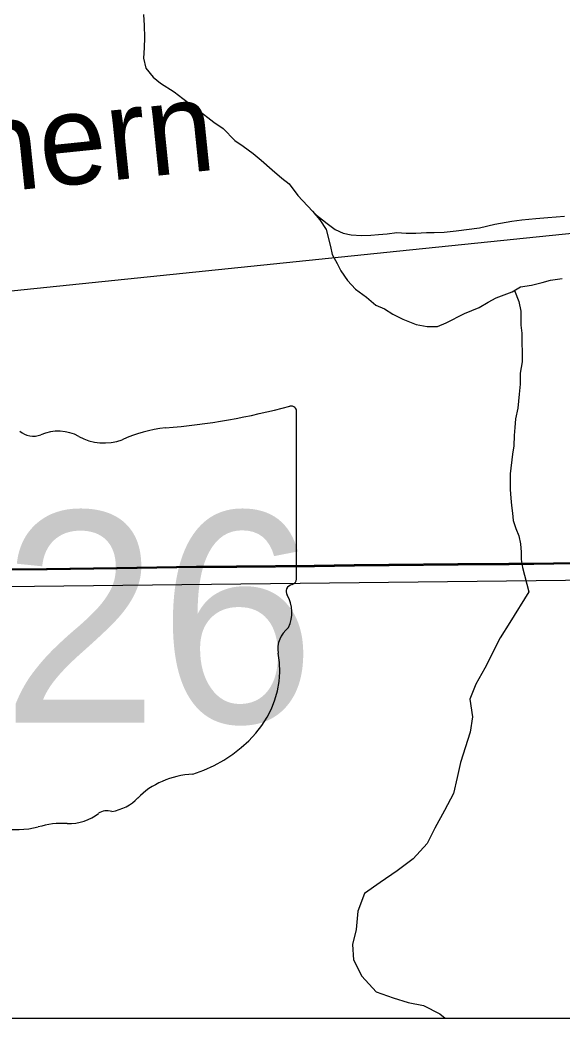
# Model space of a CAD drawing. Extents: x 0 to 34, y 0 to 22.
# Drawn here: x 5.699 to 6.037, y 14.1 to 14.723 of the extents above; entities that cross this region are included whole.
import ezdxf

# ---------------------------------------------------------------- set-up
doc = ezdxf.new("R2010")
doc.units = 0
for name, color, linetype in [('Default', 7, 'Continuous'), ('GM_X_Minor_River', 7, 'Continuous'), ('GM_X_Rail_Line', 7, 'Continuous'), ('GM_X_Rail_Line_Text', 7, 'Continuous'), ('GM_X_Section', 7, 'Continuous'), ('GM_X_State_Location', 7, 'Continuous'), ('GM_X_State_Route', 7, 'Continuous'), ('GM_X_State_Shield', 7, 'Continuous'), ('SH_Cut_Line', 7, 'Continuous'), ('SH_Data', 7, 'Continuous')]:
    doc.layers.add(name, color=color, linetype=linetype)

msp = doc.modelspace()

# ---------------------------------------------------------------- linework, layer by layer
at = {"layer": 'Default'}
for points in [[(5.67058, 14.38019), (5.71576, 14.3806), (5.75952, 14.38117), (5.80924, 14.38201), (5.83435, 14.38215), (5.88281, 14.38257), (5.90775, 14.383), (5.92928, 14.38313), (5.97233, 14.38355), (6.00415, 14.38377), (6.01966, 14.38388), (6.03203, 14.38412), (6.06612, 14.38445)], [(6.06612, 14.38445), (6.03203, 14.38412), (6.01966, 14.38388), (6.00415, 14.38377), (5.97233, 14.38355), (5.92928, 14.38313), (5.90775, 14.383), (5.88281, 14.38257), (5.83435, 14.38215), (5.80924, 14.38201), (5.75952, 14.38117), (5.71576, 14.3806), (5.67058, 14.38019)], [(3.68028, 14.09996), (8.9, 14.09996)]]:
    msp.add_lwpolyline(points, dxfattribs=at)
at = {"layer": 'GM_X_Minor_River'}
for points in [[(5.77612, 14.72673), (5.77652, 14.71988), (5.77692, 14.71227), (5.77655, 14.70581), (5.77619, 14.69935), (5.77773, 14.69326), (5.78232, 14.68756), (5.78691, 14.68375), (5.79532, 14.67842), (5.80067, 14.67424), (5.80985, 14.66739), (5.82017, 14.6594), (5.8259, 14.65559), (5.83317, 14.64798), (5.83852, 14.64455), (5.84464, 14.63999), (5.84961, 14.6358), (5.85649, 14.62971), (5.86261, 14.62439), (5.8672, 14.62096), (5.87256, 14.61374), (5.88174, 14.60384), (5.88634, 14.59852), (5.89017, 14.59243), (5.89286, 14.58178), (5.89402, 14.57684), (5.89708, 14.57113), (5.89939, 14.56657), (5.9036, 14.56048), (5.90857, 14.55516), (5.91545, 14.55021), (5.92119, 14.54526), (5.92654, 14.54298), (5.93189, 14.53955), (5.938, 14.53651), (5.94641, 14.53308), (5.95328, 14.53193), (5.95977, 14.53193), (5.96511, 14.53421), (5.97654, 14.53991), (5.98569, 14.5437), (5.99141, 14.54712), (5.99636, 14.54978), (6.00628, 14.55358), (6.01161, 14.55662), (6.01848, 14.55775), (6.02496, 14.55927), (6.0303, 14.56079), (6.03755, 14.56192)], [(5.88312, 14.60224), (5.89092, 14.59623), (5.89589, 14.59243), (5.90086, 14.59014), (5.90582, 14.589), (5.91231, 14.58862), (5.91803, 14.58899), (5.92299, 14.58937), (5.92834, 14.58975), (5.93444, 14.5905), (5.94017, 14.59012), (5.94627, 14.59012), (5.95276, 14.59049), (5.95772, 14.59049), (5.96383, 14.59087), (5.97146, 14.59162), (5.98595, 14.59351), (5.99549, 14.59579), (6.00617, 14.59769), (6.01228, 14.59844), (6.02105, 14.5992), (6.02868, 14.59995), (6.03899, 14.60071)], [(6.00776, 14.55442), (6.01049, 14.54749), (6.01165, 14.54141), (6.01167, 14.53266), (6.01244, 14.52772), (6.01248, 14.50984), (6.01136, 14.50262), (6.01137, 14.49578), (6.01062, 14.48969), (6.00988, 14.48095), (6.00837, 14.4741), (6.008, 14.46878), (6.00763, 14.46384), (6.00727, 14.45737), (6.00651, 14.45205), (6.00502, 14.43988), (6.00504, 14.43), (6.00544, 14.42467), (6.00583, 14.42011), (6.0066, 14.41517), (6.00699, 14.4106), (6.00853, 14.40566), (6.01045, 14.4011), (6.01161, 14.39615), (6.012, 14.39083), (6.01201, 14.38627), (6.01279, 14.38132), (6.01665, 14.36607)], [(6.01665, 14.36607), (6.00493, 14.34699), (5.99893, 14.33747), (5.98922, 14.31845), (5.98361, 14.30856), (5.97989, 14.29905), (5.98149, 14.28807), (5.98004, 14.27858), (5.97412, 14.25958), (5.97191, 14.25009), (5.96971, 14.24022), (5.96411, 14.22957), (5.95813, 14.21853), (5.95327, 14.20902), (5.94462, 14.19949), (5.93445, 14.19184), (5.9239, 14.18457), (5.9141, 14.17769), (5.91001, 14.16667), (5.90895, 14.15529), (5.90675, 14.14579), (5.9072, 14.13631), (5.91258, 14.12611), (5.92136, 14.11631), (5.932, 14.11258), (5.94149, 14.10961), (5.95098, 14.10777), (5.96124, 14.10253), (5.9645, 14.09996)]]:
    msp.add_lwpolyline(points, dxfattribs=at)
at = {"layer": 'GM_X_Rail_Line'}
msp.add_lwpolyline([(5.11889, 14.49521), (5.29962, 14.51377), (5.38966, 14.52305), (5.6733, 14.55209), (5.92816, 14.57822), (6.17334, 14.60341), (6.43245, 14.62993), (6.5087, 14.63828), (6.53018, 14.6412), (6.54711, 14.6439), (6.56184, 14.64656), (6.57733, 14.64967), (6.59274, 14.65332), (6.60952, 14.65764), (6.62645, 14.66273)], dxfattribs=at)
at = {"layer": 'GM_X_Section'}
msp.add_lwpolyline([(5.49662, 15.37719), (6.00137, 15.38987), (6.50804, 15.39727), (6.51868, 14.37863), (5.50533, 14.36709)], close=True, dxfattribs=at)
at = {"layer": 'GM_X_State_Route'}
msp.add_lwpolyline([(5.67079, 14.37964), (5.71597, 14.38006), (5.75973, 14.38062), (5.80945, 14.38147), (5.83456, 14.3816), (5.88302, 14.38203), (5.90796, 14.38245), (5.92949, 14.38259), (5.97254, 14.38301), (6.00436, 14.38323), (6.01987, 14.38334), (6.03224, 14.38357), (6.06633, 14.3839)], dxfattribs=at)
at = {"layer": 'GM_X_State_Shield'}
for p, q in [((5.87168, 14.37412), (5.87168, 14.47881)), ((5.87164, 14.37415), (5.87168, 14.37412))]:
    msp.add_line(p, q, dxfattribs=at)
for centre, major_axis, start_param, end_param in [((5.75427, 14.74668), (0.34952, 0), 4.814394, 5.042369), ((5.86802, 14.47924), (0.00367, 0), 6.141152, 7.989035), ((5.79886, 14.41272), (0.07032, 0), 1.699011, 2.107814), ((5.70731, 14.47187), (0.01068, 0), 3.836095, 5.185415), ((5.72299, 14.44874), (0.02221, 0), 0.950623, 2.079405), ((5.75166, 14.48046), (0.02672, 0), 4.081561, 5.145723), ((5.87083, 14.36644), (0.00568, 0), 1.883978, 3.671073), ((5.86776, 14.37372), (0.00393, 0), 5.05454, 6.418171), ((5.8347, 14.3532), (0.03409, 0), 5.934695, 6.695948), ((5.88482, 14.33031), (0.0248, 0), 2.387724, 3.262537), ((5.77385, 14.31699), (0.08742, 0), 5.101752, 6.440018), ((5.81071, 14.2141), (0.04788, 0), 1.647645, 2.488434), ((5.75005, 14.25089), (0.02824, 0), 4.937069, 5.64225), ((5.69649, 14.25775), (0.05011, 0), 4.026481, 4.996735), ((5.7291, 14.24276), (0.0267, 0), 4.691044, 5.507374), ((5.75326, 14.22338), (0.00752, 0), 1.147584, 2.315152), ((5.72544, 14.18856), (0.04118, 0), 1.495662, 1.94098)]:
    msp.add_ellipse(centre, major_axis=major_axis, ratio=0.8, start_param=start_param, end_param=end_param, dxfattribs=at)
at = {"layer": 'SH_Cut_Line'}
for points in [[(6.06612, 14.38445), (6.03203, 14.38412), (6.01966, 14.38388), (6.00415, 14.38377), (5.97233, 14.38355), (5.92928, 14.38313), (5.90775, 14.383), (5.88281, 14.38257), (5.83435, 14.38215), (5.80924, 14.38201), (5.75952, 14.38117), (5.71576, 14.3806), (5.67058, 14.38019)], [(5.67058, 14.38019), (5.71576, 14.3806), (5.75952, 14.38117), (5.80924, 14.38201), (5.83435, 14.38215), (5.88281, 14.38257), (5.90775, 14.383), (5.92928, 14.38313), (5.97233, 14.38355), (6.00415, 14.38377), (6.01966, 14.38388), (6.03203, 14.38412), (6.06612, 14.38445)], [(2.1, 14.09996), (8.9, 14.09996)]]:
    msp.add_lwpolyline(points, dxfattribs=at)
at = {"layer": 'SH_Data'}
msp.add_line((2.1, 14.09996), (8.9, 14.09996), dxfattribs=at)

# ---------------------------------------------------------------- texts
at = {"layer": 'GM_X_Rail_Line_Text'}
msp.add_text('Southern', height=0.056629, rotation=5.86699, dxfattribs=at).set_placement((5.51664, 14.59844))
at = {"layer": 'GM_X_State_Location'}
for s, p in [('s', (5.70318, 14.35704)), ('r', (5.70317, 14.35704))]:
    msp.add_text(s, height=0.000189, dxfattribs=at).set_placement(p)
at = {"layer": 'GM_X_State_Shield'}
msp.add_text('226', height=0.131836, dxfattribs=at).set_placement((5.58952, 14.2844))

doc.saveas('drawing.dxf')
